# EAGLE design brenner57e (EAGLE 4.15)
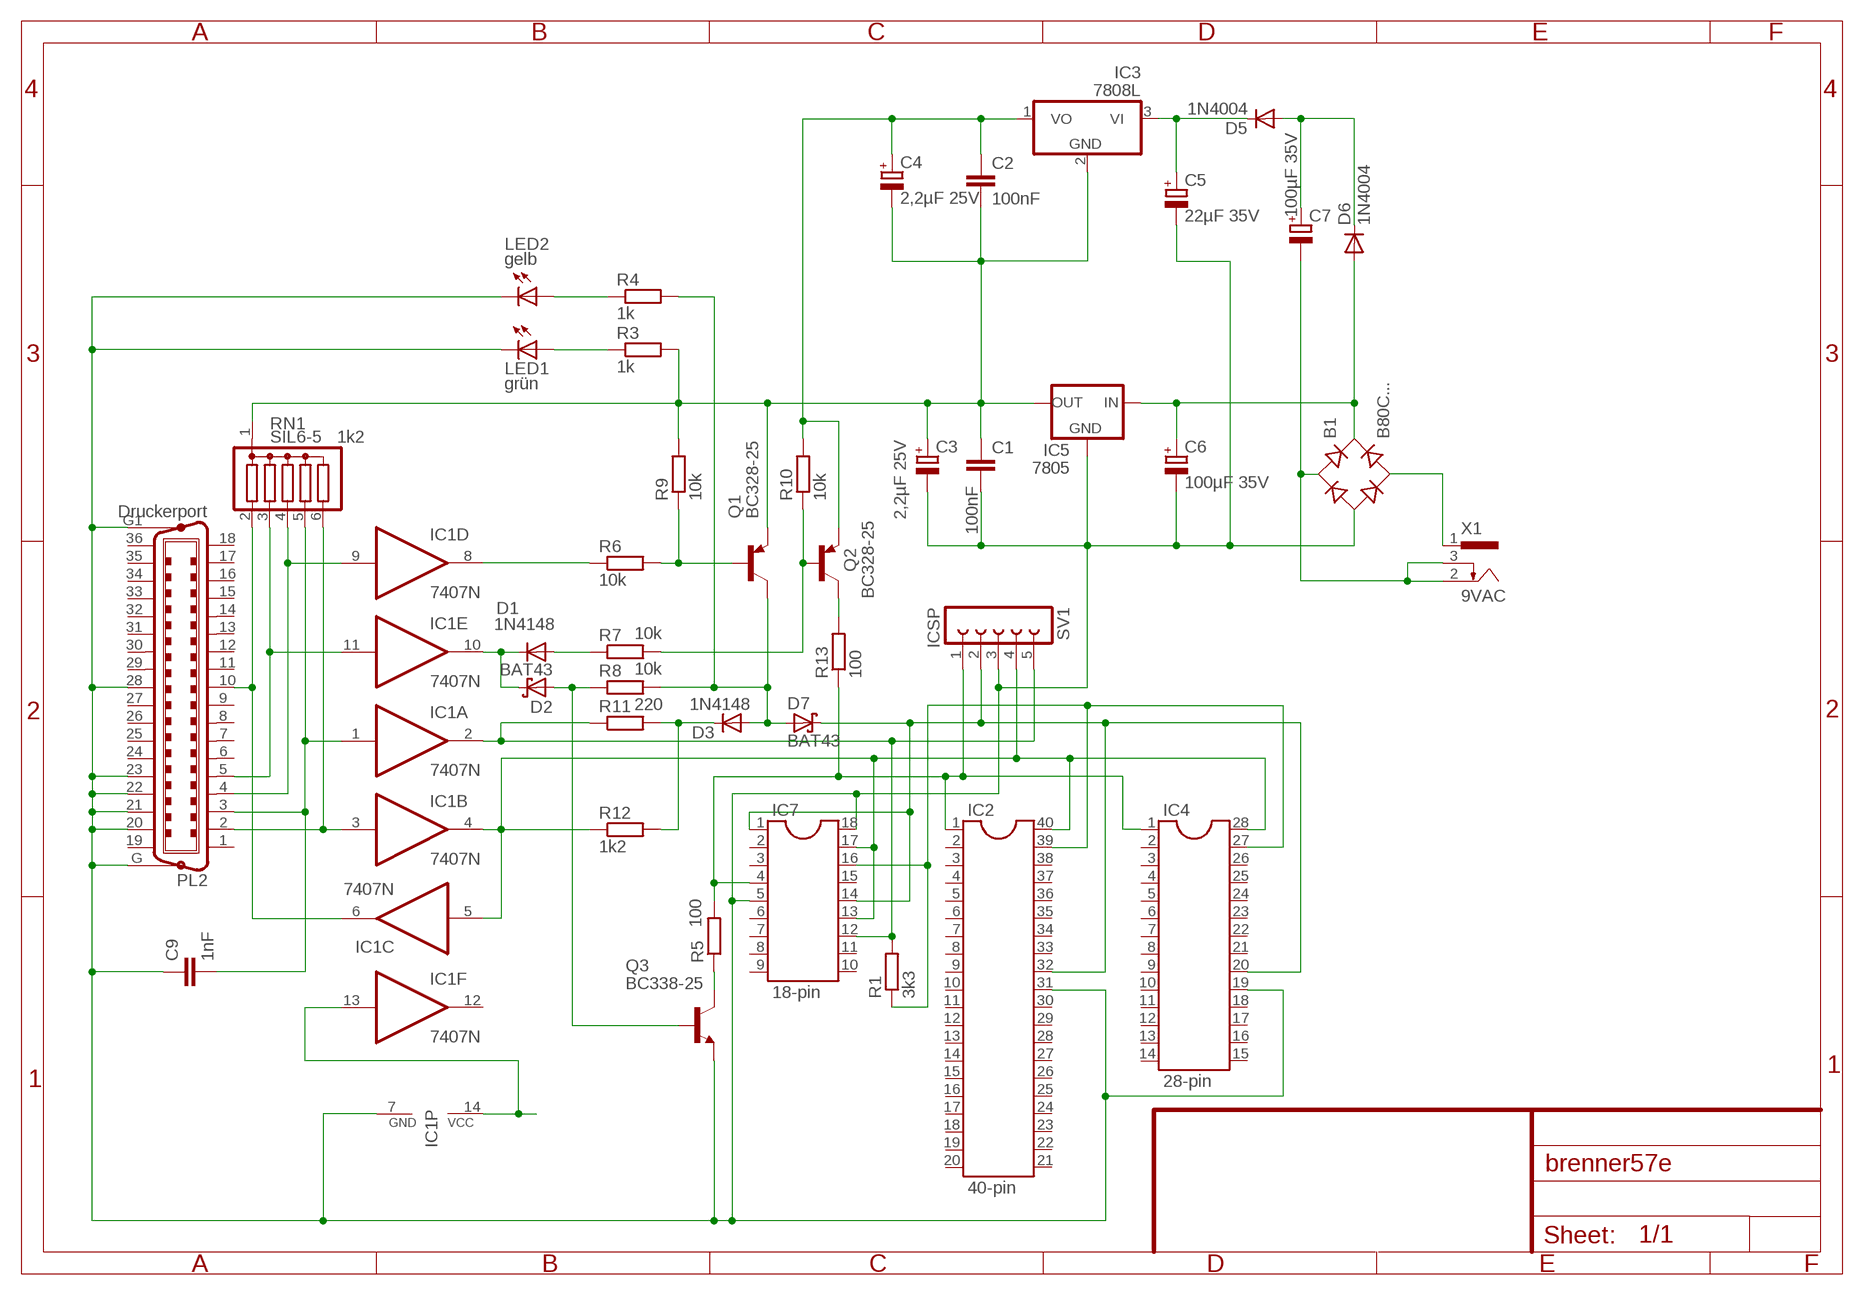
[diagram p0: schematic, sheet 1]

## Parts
B1  B80C...  RB1A  [RB1A]
C1  100nF  C-EU050-030X075  [C050-030X075]
C2  100nF  C-EU050-030X075  [C050-030X075]
C3  2,2µF 25V  CPOL-EUE2.5-5  [E2,5-5]
C4  2,2µF 25V  CPOL-EUE2.5-5  [E2,5-5]
C5  22µF 35V  CPOL-EUE5-8.5  [E5-8,5]
C6  100µF 35V  CPOL-EUE5-8.5  [E5-8,5]
C7  100µF 35V  CPOL-EUE5-8.5  [E5-8,5]
C9  1nF  C-EU050-025X075  [C050-025X075]
D1  1N4148  [DO35-10]
D2  BAT43  [DO35-10]
D3  1N4148  [DO35-10]
D5  1N4004  [DO41-10]
D6  1N4004  [DO41-10]
D7  BAT43  [DO35-10]
IC1  7407N  [DIL14]
IC2  40-pin  TEXTOOL40  [TEXTOOL40]
IC3  7808L  [TO92]
IC4  28-pin  DIL28-3  [DIL28-3]
IC5  7805  78XXS  [78XXS]
IC7  18-pin  TEXTOOL18  [TEXTOOL18]
LED1  grün  LED5MM  [LED5MM]
LED2  gelb  LED5MM  [LED5MM]
PL2  Druckerport  C36HP  [36HP]
Q1  BC328-25  [TO92-EBC]
Q2  BC328-25  [TO92-EBC]
Q3  BC338-25  [TO92-EBC]
R1  3k3  R-EU_0207/10  [0207/10]
R3  1k  R-EU_0207/10  [0207/10]
R4  1k  R-EU_0207/10  [0207/10]
R5  100  R-EU_0207/10  [0207/10]
R6  10k  R-EU_0207/10  [0207/10]
R7  10k  R-EU_0207/10  [0207/10]
R8  10k  R-EU_0207/10  [0207/10]
R9  10k  R-EU_0207/10  [0207/10]
R10  10k  R-EU_0207/10  [0207/10]
R11  220  R-EU_0207/10  [0207/10]
R12  1k2  R-EU_0207/10  [0207/10]
R13  100  R-EU_0207/10  [0207/10]
RN1  SIL6-5 1k2  G05R  [SIL6]
SV1  ICSP  FE05-1  [FE05-1]
X1  9VAC  733989-55  [733989-5]

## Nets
5VGESCH: D3.A D7.A Q1.C R4.2 R8.2
13V: C2.1 C4.+ IC3.1(VO) Q2.E R10.2
DATA_IN: IC1.3(B:I) PL2.2 RN1.6
DATA_OUT: IC1.6(C:O) PL2.10 RN1.2
GND [GND]: B1.- C1.2 C3.- C5.- C6.- C9.1 IC1.7(P:GND) IC2.31 IC4.19 IC5.GND IC7.5 IC7.18 LED1.K(C) LED2.K(C) PL2.20 PL2.21 PL2.22 PL2.23 PL2.28 PL2.G PL2.G1 Q3.E SV1.3
ICSP_CLK: IC1.2(A:O) IC7.12 R1.2 R11.1 SV1.5
ICSP_DATA: IC1.4(B:O) IC1.5(C:I) IC2.40 IC4.28 IC7.13 IC7.17 R12.1 SV1.4
MCLR: IC2.1 IC4.1 IC7.4 R5.2 R13.1 SV1.1
N$1: IC1.9(D:I) PL2.4 RN1.4
N$2: IC1.11(E:I) PL2.5 RN1.3
N$3: C9.2 IC1.1(A:I) PL2.3 RN1.5
N$4: D3.C R11.2 R12.2
N$5: IC2.39 IC4.27 IC7.16 R1.1
N$6: IC1.8(D:O) R6.1
N$7: B1.+ C6.+ D6.A IC5.IN
N$8: Q2.C R13.2
N$9: B1.AC1 C7.- X1.2 X1.3
N$10: C5.+ D5.C IC3.3(VI)
N$11: C7.+ D5.A D6.C
N$12: Q3.C R5.1
N$13: B1.AC2 X1.1
N$14: D1.C D2.C IC1.10(E:O)
N$15: LED1.A R3.1
N$16: LED2.A R4.1
N$17: Q1.B R6.2 R9.1
N$18: D1.A R7.1
N$19: Q2.B R7.2 R10.1
N$21: D2.A Q3.B R8.1
VCC [GND]: C1.1 C2.2 C3.+ C4.- IC1.13(F:I) IC1.14(P:VCC) IC3.2(GND) IC5.OUT Q1.E R3.2 R9.2 RN1.1
VDD: D7.C IC2.32 IC4.20 IC7.1 IC7.14 SV1.2
Unconnected: IC1.12(F:O) IC2.2 IC2.3 IC2.4 IC2.5 IC2.6 IC2.7 IC2.8 IC2.9 IC2.10 IC2.11 IC2.12 IC2.13 IC2.14 IC2.15 IC2.16 IC2.17 IC2.18 IC2.19 IC2.20 IC2.21 IC2.22 IC2.23 IC2.24 IC2.25 IC2.26 IC2.27 IC2.28 IC2.29 IC2.30 IC2.33 IC2.34 IC2.35 IC2.36 IC2.37 IC2.38 IC4.2 IC4.3 IC4.4 IC4.5 IC4.6 IC4.7 IC4.8 IC4.9 IC4.10 IC4.11 IC4.12 IC4.13 IC4.14 IC4.15 IC4.16 IC4.17 IC4.18 IC4.21 IC4.22 IC4.23 IC4.24 IC4.25 IC4.26 IC7.2 IC7.3 IC7.6 IC7.7 IC7.8 IC7.9 IC7.10 IC7.11 IC7.15 PL2.1 PL2.6 PL2.7 PL2.8 PL2.9 PL2.11 PL2.12 PL2.13 PL2.14 PL2.15 PL2.16 PL2.17 PL2.18 PL2.19 PL2.24 PL2.25 PL2.26 PL2.27 PL2.29 PL2.30 PL2.31 PL2.32 PL2.33 PL2.34 PL2.35 PL2.36

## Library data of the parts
B1 = rectifier:RB1A: RECTIFIER 1 A
C1 C2 C9 = rcl:C-EU: CAPACITOR, European symbol
C3-C7 = rcl:CPOL-EU: POLARIZED CAPACITOR, European symbol
D1 D3 = diode:1N4148: DIODE
D2 D7 = sprut:BAT43: DIODE
D5 D6 = diode:1N4004: DIODE
IC1 = 74xx-eu:74*07: Hex BUFFER, open collector high-voltage output
IC2 = sprut:TEXTOOL40: Dual In Line
IC3 = linear:78*: Positive VOLTAGE REGULATOR
IC4 = ic-package:DIL28: Dual In Line
IC5 = v-reg:78XXS: VOLTAGE REGULATOR
IC7 = sprut:TEXTOOL18: Dual In Line
LED1 LED2 = led:LED: LED
PL2 = con-amp-champ:C36HP: CONNECTOR
Q1 Q2 = transistor-pnp:BC328*: PNP Transistror
Q3 = transistor-npn:BC338*: NPN Transistor
R1 R3-R13 = rcl:R-EU_: RESISTOR, European symbol
RN1 = resistor-sil:G05R: SIL RESISTOR
SV1 = con-lsta:FE05-1: FEMALE HEADER
X1 = con-conrad:733989-55: FEMALE PRINT CONNECTOR 1.1 mm, FUK HING Industries, distributor Conrad

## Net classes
1 GND: width 1.016 mm

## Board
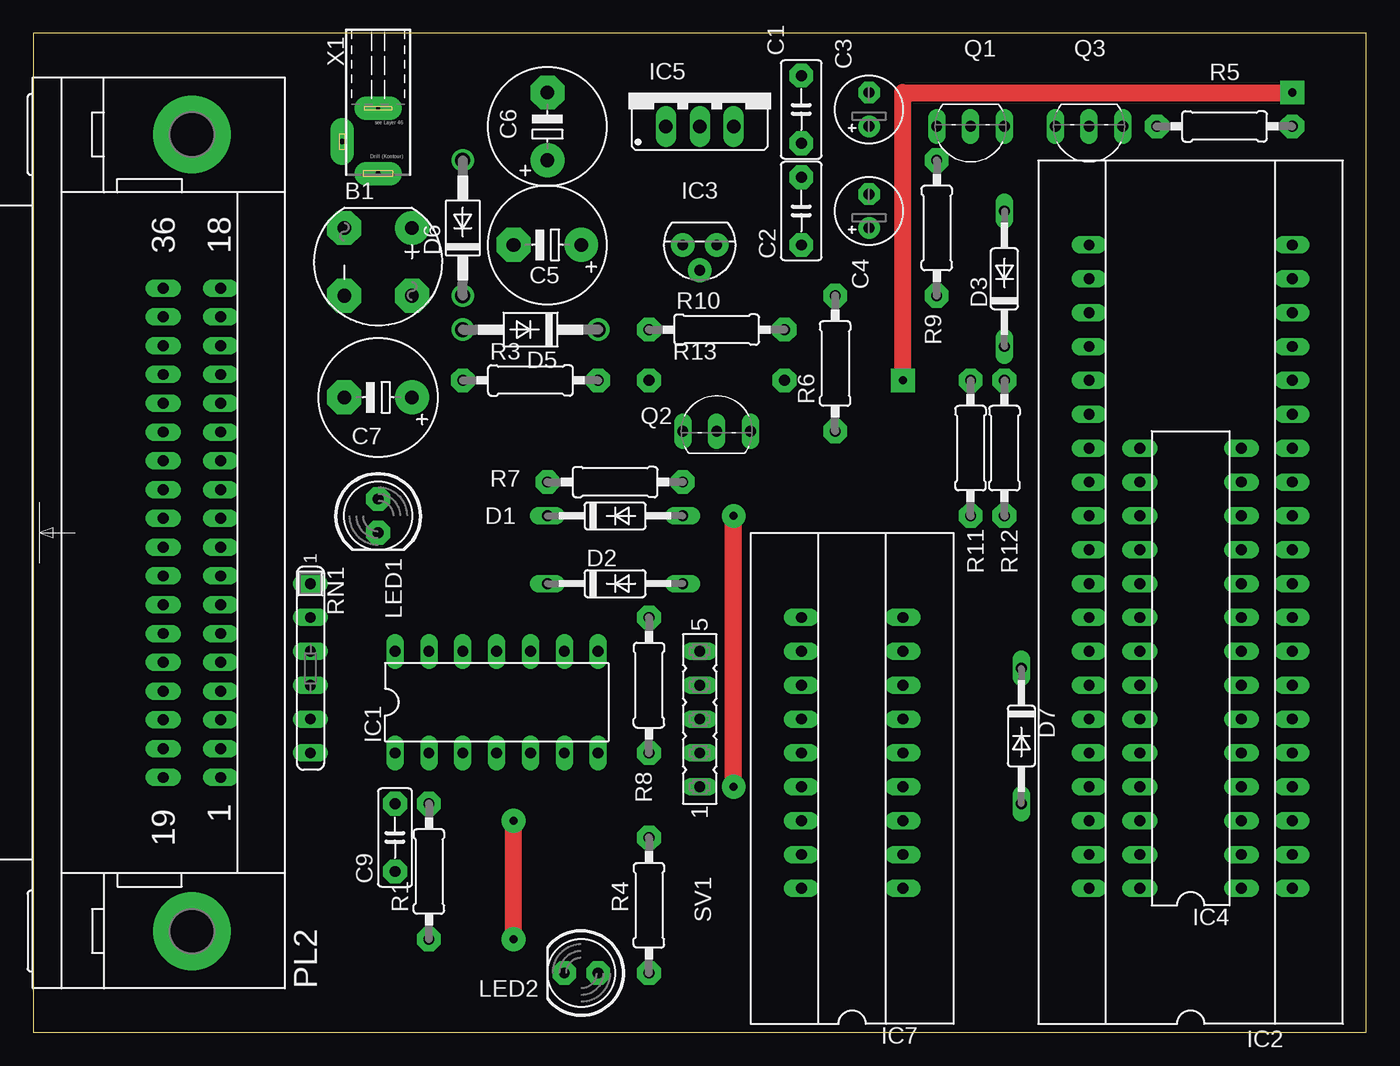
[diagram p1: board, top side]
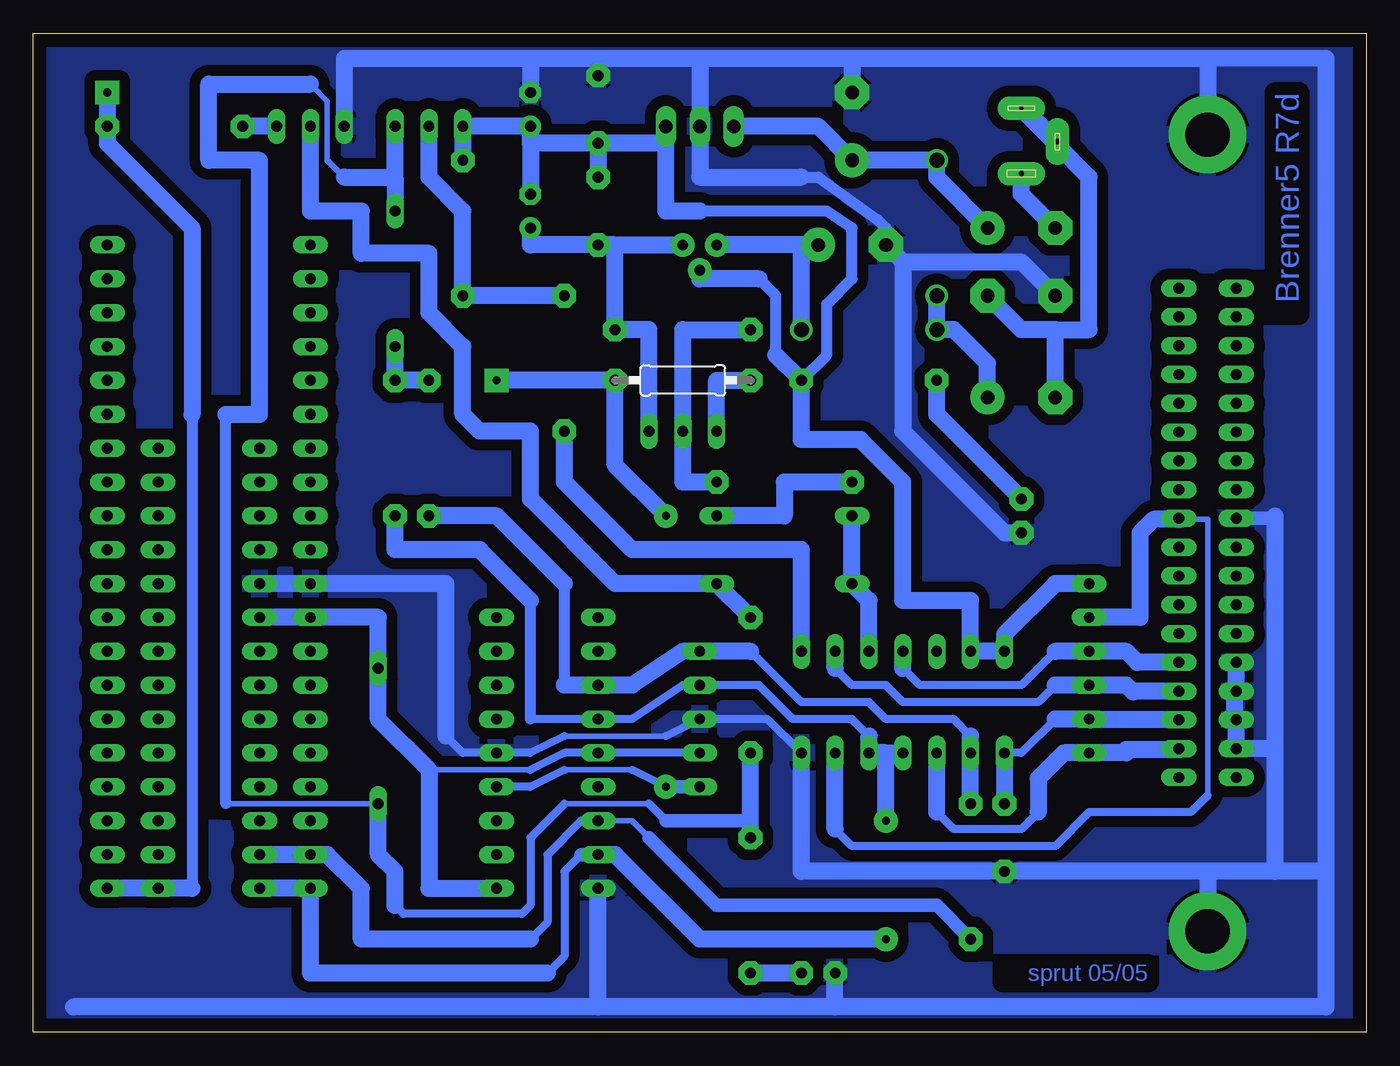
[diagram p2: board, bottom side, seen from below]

Size 100 x 74.92 mm. Coordinates in mm from the lower left corner, seen from the top.
Outline: 0,0 100,0 100,74.92 0,74.92 0,0
Copper layers (1*16): Top 0.035mm / dielectric 1.5mm / Bottom 0.035mm
Design rules "leiterplatte mit löchern": minimum track width 10mil, minimum drill 8mil, track to track 8mil, track to pad 8mil, pad to pad 8mil, via to via 8mil, smd to smd 8mil, copper to edge 40mil, drill to drill 8mil, minimum pad ring 10mil, minimum via ring 10mil, stop-mask expansion 4mil, vias tented up to drill 0mil, thermal gap 10mil

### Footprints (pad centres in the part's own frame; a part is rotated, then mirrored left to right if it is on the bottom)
RB1A = drill 1.016 pad 2.54 round: + -2.54,2.54 | drill 1.016 pad 2.54 octagon: - 2.54,-2.54; AC1 2.54,2.54; AC2 -2.54,-2.54
C050-030X075 = drill 0.813 pad 1.778 octagon: 1 -2.54,0; 2 2.54,0
E2,5-5 = drill 0.813 pad 1.6 round: + -1.27,0 | drill 0.813 pad 1.6 octagon: - 1.27,0
E5-8,5 = drill 1.016 pad 2.54 round: + -2.54,0 | drill 1.016 pad 2.54 octagon: - 2.54,0
C050-025X075 = drill 0.813 pad 1.778 octagon: 1 -2.54,0; 2 2.54,0
DO35-10 = drill 0.813 long: A 5.08,0; C -5.08,0
DO41-10 = drill 1.118 round: A 5.08,0; C -5.08,0
DIL14 = drill 0.813 long: 1 -7.62,-3.81; 2 -5.08,-3.81; 3 -2.54,-3.81; 4 0,-3.81; 5 2.54,-3.81; 6 5.08,-3.81; 7 7.62,-3.81; 8 7.62,3.81; 9 5.08,3.81; 10 2.54,3.81; 11 0,3.81; 12 -2.54,3.81; 13 -5.08,3.81; 14 -7.62,3.81
TEXTOOL40 = drill 0.813 long: 1 -24.13,-7.62; 2 -21.59,-7.62; 3 -19.05,-7.62; 4 -16.51,-7.62; 5 -13.97,-7.62; 6 -11.43,-7.62; 7 -8.89,-7.62; 8 -6.35,-7.62; 9 -3.81,-7.62; 10 -1.27,-7.62; 11 1.27,-7.62; 12 3.81,-7.62; 13 6.35,-7.62; 14 8.89,-7.62; 15 11.43,-7.62; 16 13.97,-7.62; 17 16.51,-7.62; 18 19.05,-7.62; 19 21.59,-7.62; 20 24.13,-7.62; 21 24.13,7.62; 22 21.59,7.62; 23 19.05,7.62; 24 16.51,7.62; 25 13.97,7.62; 26 11.43,7.62; 27 8.89,7.62; 28 6.35,7.62; 29 3.81,7.62; 30 1.27,7.62; 31 -1.27,7.62; 32 -3.81,7.62; 33 -6.35,7.62; 34 -8.89,7.62; 35 -11.43,7.62; 36 -13.97,7.62; 37 -16.51,7.62; 38 -19.05,7.62; 39 -21.59,7.62; 40 -24.13,7.62
TO92 = drill 0.813 pad 1.778 round: 1 -1.27,0; 2 0,1.905; 3 1.27,0
DIL28-3 = drill 0.813 long: 1 -16.51,-3.81; 2 -13.97,-3.81; 3 -11.43,-3.81; 4 -8.89,-3.81; 5 -6.35,-3.81; 6 -3.81,-3.81; 7 -1.27,-3.81; 8 1.27,-3.81; 9 3.81,-3.81; 10 6.35,-3.81; 11 8.89,-3.81; 12 11.43,-3.81; 13 13.97,-3.81; 14 16.51,-3.81; 15 16.51,3.81; 16 13.97,3.81; 17 11.43,3.81; 18 8.89,3.81; 19 6.35,3.81; 20 3.81,3.81; 21 1.27,3.81; 22 -1.27,3.81; 23 -3.81,3.81; 24 -6.35,3.81; 25 -8.89,3.81; 26 -11.43,3.81; 27 -13.97,3.81; 28 -16.51,3.81
78XXS = drill 1.016 long: GND 0,-2.54; IN -2.54,-2.54; OUT 2.54,-2.54
TEXTOOL18 = drill 0.813 long: 1 -10.16,-3.81; 2 -7.62,-3.81; 3 -5.08,-3.81; 4 -2.54,-3.81; 5 0,-3.81; 6 2.54,-3.81; 7 5.08,-3.81; 8 7.62,-3.81; 9 10.16,-3.81; 10 10.16,3.81; 11 7.62,3.81; 12 5.08,3.81; 13 2.54,3.81; 14 0,3.81; 15 -2.54,3.81; 16 -5.08,3.81; 17 -7.62,3.81; 18 -10.16,3.81
LED5MM = drill 0.813 pad 1.778 octagon: A -1.27,0; K 1.27,0
36HP = drill 0.813 long: 1 -18.352,-2.159; 2 -16.192,-2.159; 3 -14.034,-2.159; 4 -11.874,-2.159; 5 -9.716,-2.159; 6 -7.556,-2.159; 7 -5.397,-2.159; 8 -3.239,-2.159; 9 -1.079,-2.159; 10 1.079,-2.159; 11 3.239,-2.159; 12 5.397,-2.159; 13 7.556,-2.159; 14 9.716,-2.159; 15 11.874,-2.159; 16 14.034,-2.159; 17 16.192,-2.159; 18 18.352,-2.159; 19 -18.352,2.159; 20 -16.192,2.159; 21 -14.034,2.159; 22 -11.874,2.159; 23 -9.716,2.159; 24 -7.556,2.159; 25 -5.397,2.159; 26 -3.239,2.159; 27 -1.079,2.159; 28 1.079,2.159; 29 3.239,2.159; 30 5.397,2.159; 31 7.556,2.159; 32 9.716,2.159; 33 11.874,2.159; 34 14.034,2.159; 35 16.192,2.159; 36 18.352,2.159 | drill 3.302 pad 5.842 round: G -29.87,0; G1 29.87,0
TO92-EBC = drill 0.813 long: B 0,-1.27; C -2.54,-1.27; E 2.54,-1.27
0207/10 = drill 0.813 pad 1.778 octagon: 1 -5.08,0; 2 5.08,0
SIL6 = drill 0.813 long: 1 -6.35,0; 2 -3.81,0; 3 -1.27,0; 4 1.27,0; 5 3.81,0; 6 6.35,0
FE05-1 = drill 0.813 long: 1 -5.08,0; 2 -2.54,0; 3 0,0; 4 2.54,0; 5 5.08,0
733989-5 = drill 0.4 pad 1.778 long: 1 0,5.82; 3 2.7,3.42 | drill 0.3 pad 1.778 long: 2 0,0.92

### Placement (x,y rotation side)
B1  25.87,57.78 270 top
C1  57.62,69.21 90 top
C2  57.62,61.59 90 top
C3  62.7,69.21 90 top
C4  62.7,61.59 90 top
C5  38.57,59.05 180 top
C6  38.57,67.94 90 top
C7  25.87,47.62 180 top
C9  27.14,14.6 90 top
D1  43.65,38.73 0 top
D2  43.65,33.65 0 top
D3  72.86,56.51 90 top
D5  37.3,52.7 180 top
D6  32.22,60.32 90 top
D7  74.13,22.22 270 top
IC1  34.76,24.76 0 top
IC2  86.83,34.92 90 top
IC3  50,59.05 180 top
IC4  86.83,27.3 90 top
IC5  50,70.48 0 top
IC7  61.43,20.95 90 top
LED1  25.87,38.73 270 top
LED2  41.11,4.44 180 top
PL2  11.9,37.46 90 top
Q1  70.32,66.67 180 top
Q2  51.27,46.35 0 top
Q3  79.21,66.67 180 top
R1  29.68,12.06 90 top
R3  37.3,48.89 0 top
R4  46.19,9.52 90 top
R5  89.37,67.94 0 top
R6  60.16,50.16 90 top
R7  43.65,41.27 0 top
R8  46.19,26.03 270 top
R9  67.78,60.32 90 top
R10  51.27,52.7 0 top
R11  70.32,43.81 90 top
R12  72.86,43.81 90 top
R13  51.27,48.89 0 bottom
RN1  20.79,27.3 270 top
SV1  50,23.49 90 top
X1  25.87,70.23 180 top

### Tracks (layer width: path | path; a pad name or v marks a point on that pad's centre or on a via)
5VGESCH
  Bottom 0.406: 53.81,17.14 60.16,17.14 | 76.67,64.13 77.94,65.4 77.94,69.84 79.21,71.12 | D7.A 85.56,17.14
  Bottom 0.61: 72.86,9.52 72.22,8.88 63.34,8.88 62.7,9.52 62.7,14.6 60.16,17.14 | R4.2 46.19,15.87 | 52.54,15.87 53.81,17.14
  Bottom 0.813: 85.56,17.14 85.56,46.35
  Bottom 1.016: 46.19,15.87 52.54,15.87
  Bottom 1.27: R4.2 R8.2 | 72.86,9.52 72.86,12.06 74.13,13.33 D7.A | 72.86,64.13 Q1.C | 72.86,64.13 D3.A | 76.67,64.13 72.86,64.13 | 79.21,71.12 86.83,71.12 86.83,65.4 83.02,65.4 83.02,46.35 85.56,46.35
13V
  Bottom 1.27: 56.35,59.05 IC3.1 | 56.35,59.05 C2.1 62.7,59.05 C4.+ | 56.35,59.05 R10.2 53.81,52.7 Q2.E
DATA_IN
  Bottom 0.406: 18,20.95 17.87,21.08 17.74,21.2
  Bottom 0.61: 24.6,16.5 25.87,15.23 30.95,15.23 32.22,16.5 | 18,21.2 17.87,21.08 | 13.93,21.2 14,21.27 PL2.2
  Bottom 1.27: 18,20.95 RN1.6 22.7,20.95 24.6,19.04 24.6,16.5 | 32.22,16.5 IC1.3 | 13.93,21.2 18,21.2
DATA_OUT
  Bottom 0.406: 11.9,17.77 11.9,38.48 13.93,38.48
  Bottom 0.61: 11.9,17.77 13.17,16.5 20.79,16.5 23.33,13.96 38.57,13.96 39.84,15.23
  Bottom 1.27: 39.84,15.23 IC1.6 | RN1.2 16.98,31.11 16.98,37.46 15.96,38.48 14.19,38.48 14.12,38.54 PL2.10 14,38.54 13.93,38.48
GND
  Bottom 0.406: 52.54,22.22 60.16,22.22 | 6.82,38.73 7.01,38.54
  Bottom 0.61: IC1.7 44.92,23.49 SV1.3 52.54,22.22 | 60.16,22.22 62.7,20.95 IC7.5 67.78,20.95 69.05,22.22 | PL2.28 9.55,38.54 9.36,38.73 9.17,38.54 | 9.87,25.52 9.81,25.59 | 9.81,25.59 PL2.22 | 9.81,25.59 9.74,25.65 | 9.87,23.49 9.81,23.43 PL2.21 | 9.81,21.27 9.87,21.2 | PL2.20 9.81,21.27 | 9.81,21.27 9.74,21.33 | 6.82,21.2 6.88,21.27 | 3.01,73.02 3.04,73.05
  Bottom 0.813: C5.- 36.03,60.32 36.66,60.96 41.11,64.13 42.38,64.13
  Bottom 1.016: 7.01,38.54 9.17,38.54
  Bottom 1.27: 69.05,22.22 69.05,33.65 IC2.31 IC4.19 | 6.82,12.06 11.9,12.06 | 11.9,12.06 C9.1 42.38,12.06 IC1.7 | 6.82,12.06 6.82,21.2 6.82,38.73 | 39.84,1.9 3.01,1.9 3.01,12.06 | 39.84,1.9 57.62,1.9 | 57.62,1.9 96.99,1.9 | 3.01,12.06 3.01,73.02 | 3.01,12.06 6.82,12.06 | 57.62,1.9 IC7.18 | 39.84,1.9 LED2.K | 11.9,12.06 PL2.G | 9.74,25.65 PL2.23 | 9.87,23.49 9.87,25.52 | 9.74,21.33 PL2.21 | 6.88,21.27 PL2.20 | 38.57,73.02 C6.- | 38.57,73.02 50,73.02 | 50,73.02 IC5.GND 50,64.13 42.38,64.13 | B1.- 25.87,57.78 34.76,57.78 | C5.- 34.76,57.78 | 3.04,73.05 11.9,73.02 | 11.9,73.02 PL2.G1 | 57.62,73.02 C1.2 | 62.7,73.02 C3.- | 57.62,73.02 62.7,73.02 | 50,73.02 57.62,73.02 | Q3.E 76.67,73.02 62.7,73.02 | 11.9,73.02 38.57,73.02 | LED1.K 27.14,37.46 34.76,45.08 34.76,57.78
  pour Bottom (isolate 0.813): -0.8,-0.64 100.8,-0.64 100.8,75.56 -0.8,75.56
ICSP_CLK
  Bottom 0.61: 46.19,28.57 42.38,24.76 37.3,24.76 36.03,23.49 30.95,23.49 29.68,22.22
  Bottom 0.813: 60.16,26.03 60.16,33.65
  Bottom 1.27: 46.19,28.57 SV1.5 51.27,28.57 55.08,26.03 IC7.12 60.16,26.03 | 29.68,22.22 IC1.2 R1.2 | 60.16,33.65 65.24,38.73 R11.1
ICSP_DATA  (via drill 0.61 pad 1.78)
  Top 1.27: v36.03,6.98 v36.03,15.87
  Bottom 0.61: 37.3,22.22 38.57,23.49 43.02,23.49 45.55,26.03 SV1.4 51.27,26.03 55.08,23.49 IC7.13 62.7,23.49 | 58.89,13.33 60.16,12.06 60.16,5.71 61.43,4.44
  Bottom 0.813: 62.7,23.49 62.7,32.38
  Bottom 1.016: IC7.17 58.89,13.33
  Bottom 1.27: 36.03,20.95 IC1.4 | 36.03,20.95 IC1.5 37.3,22.22 | 62.7,32.38 66.51,36.19 72.86,36.19 R12.1 | IC4.28 IC2.40 79.21,4.44 61.43,4.44 | IC7.17 56.35,13.33 50,6.98 v36.03,6.98 | v36.03,15.87 36.03,20.95
MCLR  (via drill 0.61 pad 1.78)
  Top 1.27: v52.54,18.41 v52.54,38.73 | v65.24,48.89 65.24,70.48 v94.45,70.48
  Bottom 0.406: 55.08,19.68 60.16,19.68
  Bottom 0.61: v52.54,18.41 55.08,19.68 | 60.16,19.68 62.7,18.41 IC7.4
  Bottom 0.813: 88.1,46.35 88.1,10.79
  Bottom 1.016: SV1.1 v52.54,18.41
  Bottom 1.27: IC2.1 IC4.1 88.1,10.79 | 88.1,46.35 88.1,60.32 94.45,66.67 R5.2 v94.45,70.48 | v52.54,38.73 56.35,42.54 R13.1 v65.24,48.89
N$1
  Bottom 0.61: 23.33,26.03 24.6,24.76 34.76,24.76 36.03,26.03 38.57,26.03 39.84,27.3 | 17.42,25.59 17.49,25.52 | PL2.4 14,25.59 13.93,25.52
  Bottom 1.27: 17.49,25.52 18,26.03 RN1.4 23.33,26.03 | 39.84,27.3 IC1.9 | 14,25.59 17.42,25.59
N$2
  Bottom 0.61: 23.33,28.57 25.87,26.03 33.49,26.03 34.76,27.3 | 17.17,27.74 17.23,27.81 | PL2.5 14,27.74 13.93,27.81
  Bottom 1.27: 17.23,27.81 18,28.57 RN1.3 23.33,28.57 | 34.76,27.3 IC1.11 | 14,27.74 17.17,27.74
N$3
  Bottom 0.61: 23.33,23.49 25.87,20.95 IC1.1 | 20.73,23.43 RN1.5 | PL2.3 14,23.43 13.93,23.49
  Bottom 1.27: RN1.5 23.33,23.49 | IC1.1 C9.2 | 14,23.43 20.73,23.43
N$4
  Bottom 1.27: R11.2 R12.2 D3.C
N$5
  Bottom 0.406: 53.81,14.6 55.08,15.87 IC7.16 58.89,15.87
  Bottom 0.61: 58.89,15.87 61.43,13.33 61.43,8.25 62.7,6.98
  Bottom 1.016: R1.1 32.22,9.52 48.73,9.52 53.81,14.6
  Bottom 1.27: IC4.27 IC2.39 77.94,13.33 75.4,10.79 75.4,6.98 62.7,6.98
N$6
  Bottom 1.27: R6.1 60.16,41.27 55.08,36.19 42.38,36.19 IC1.8
N$7
  Bottom 1.27: IC5.IN 41.11,67.94 C6.+ D6.A 32.22,64.13 B1.+
N$8
  Bottom 1.27: Q2.C 48.73,48.89 R13.2
N$9
  Bottom 0.61: X1.2 25.97,69.31 25.87,69.21 | 25.73,69.35 23.33,66.67 | 23.17,66.51 X1.3
  Bottom 1.27: 23.33,52.7 25.87,52.7 B1.AC1 | C7.- 23.33,52.7 | X1.3 25.73,69.35 | 23.33,66.67 25.87,69.21 | 23.17,66.51 20.79,64.13 20.79,52.7 23.33,52.7
N$10
  Bottom 1.27: D5.C 42.38,59.05 C5.+ IC3.3
N$11
  Bottom 1.27: D6.C D5.A 30.95,52.7 28.41,50.16 C7.+
N$12
  Bottom 1.27: Q3.C R5.1
N$13
  Bottom 1.27: B1.AC2 25.87,62.86 X1.1
N$14
  Bottom 1.27: IC1.10 37.3,32.38 D2.C D1.C
N$15
  Bottom 1.27: LED1.A 32.22,46.35 R3.1
N$16
  Bottom 1.27: LED2.A R4.1
N$17
  Bottom 1.27: Q1.B 70.32,64.13 67.78,61.59 R9.1 R6.2
N$18
  Bottom 1.27: R7.1 43.65,41.27 43.65,38.73 D1.A
N$19
  Bottom 1.27: R10.1 51.27,52.7 Q2.B 51.27,41.27 R7.2
N$21
  Bottom 1.27: Q3.B 79.21,61.59 75.4,61.59 75.4,58.42 70.32,58.42 70.32,53.97 67.78,51.43 67.78,46.35 66.51,45.08 62.7,45.08 62.7,40 56.35,33.65 D2.A R8.1
VCC
  Bottom 0.813: 50,61.59 40.48,61.59 38.57,60.32 38.57,56.51 40.48,54.61 40.48,50.8 R3.2 | 45.55,56.51 44.28,55.24 44.28,50.8
  Bottom 1.27: IC1.14 IC1.13 | IC1.14 27.14,29.84 23.33,33.65 RN1.1 | IC1.14 IC1.13 | IC1.13 29.68,32.38 34.76,32.38 34.76,41.27 37.94,44.45 42.38,44.45 R3.2 44.28,50.8 | 50,61.59 52.54,61.59 52.54,66.67 | 52.54,66.67 IC5.OUT | C1.1 C2.2 | 52.54,66.67 C1.1 | C1.1 62.7,66.67 | 62.7,66.67 C3.+ Q1.E R9.2 | 62.7,66.67 C4.- | 45.55,56.51 50,56.51 IC3.2
VDD
  Bottom 0.406: 62.7,19.68 70.32,19.68
  Bottom 0.61: 62.7,19.68 60.16,20.95 IC7.14 SV1.2
  Bottom 1.27: IC4.20 IC2.32 74.13,31.11 D7.C 74.13,23.49 70.32,19.68 70.32,10.79 IC7.1

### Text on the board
Bottom: Brenner5 R7d | sprut 05/05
